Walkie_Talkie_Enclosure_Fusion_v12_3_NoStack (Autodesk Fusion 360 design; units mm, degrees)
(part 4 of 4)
sketch "Flex Rib 1.4 mm Sketch" plane through (0, 0, 0) normal (0, 0, 1) x axis (1, 0, 0)
  line L1 (16.2, 11) -> (13.8, 11)
  line L2 (17, 24.2) -> (17, 11.8)
  line L3 (13.8, 25) -> (16.2, 25)
  line L4 (13, 11.8) -> (13, 24.2)
  arc A1 centre (16.2, 11.8) radius 0.8 clockwise from (17, 11.8) to (16.2, 11)
  arc A2 centre (16.2, 24.2) radius 0.8 clockwise from (16.2, 25) to (17, 24.2)
  arc A3 centre (13.8, 24.2) radius 0.8 clockwise from (13, 24.2) to (13.8, 25)
  arc A4 centre (13.8, 11.8) radius 0.8 clockwise from (13.8, 11) to (13, 11.8)
extrude "Extrude14" add sketch "Flex Rib 1.4 mm Sketch" blind 1.4
sketch "LEFT PTT BUTTON Cap Sketch" plane through (0, 0, 0) normal (1, 0, 0) x axis (0, 0, -1)
  line L1 (-11.9, -15) -> (-12.1, -15)
  line L2 (-6, 33.1) -> (-6, -9.1)
  line L3 (-12.1, 39) -> (-11.9, 39)
  line L4 (-18, -9.1) -> (-18, 33.1)
  arc A1 centre (-11.9, -9.1) radius 5.9 clockwise from (-6, -9.1) to (-11.9, -15)
  arc A2 centre (-11.9, 33.1) radius 5.9 clockwise from (-11.9, 39) to (-6, 33.1)
  arc A3 centre (-12.1, 33.1) radius 5.9 clockwise from (-18, 33.1) to (-12.1, 39)
  arc A4 centre (-12.1, -9.1) radius 5.9 clockwise from (-12.1, -15) to (-18, -9.1)
extrude "Extrude1" new body sketch "LEFT PTT BUTTON Cap Sketch" blind -1.7 (= "-( 1.70 mm )") from offset 41
fillet "Fillet1" radius 1.2
sketch "LEFT PTT BUTTON End Guide Shoe Sketch" plane through (0, 0, 0) normal (1, 0, 0) x axis (0, 0, -1)
  line L1 (-8.2, -8.6) -> (-15.8, -8.6)
  line L2 (-7.7, -7.9) -> (-7.7, -8.1)
  line L3 (-15.8, -7.4) -> (-8.2, -7.4)
  line L4 (-16.3, -8.1) -> (-16.3, -7.9)
  arc A1 centre (-8.2, -8.1) radius 0.5 clockwise from (-7.7, -8.1) to (-8.2, -8.6)
  arc A2 centre (-8.2, -7.9) radius 0.5 clockwise from (-8.2, -7.4) to (-7.7, -7.9)
  arc A3 centre (-15.8, -7.9) radius 0.5 clockwise from (-16.3, -7.9) to (-15.8, -7.4)
  arc A4 centre (-15.8, -8.1) radius 0.5 clockwise from (-15.8, -8.6) to (-16.3, -8.1)
extrude "Extrude2" add sketch "LEFT PTT BUTTON End Guide Shoe Sketch" blind 3.75 from offset 35.75
sketch "LEFT PTT BUTTON Captive End Flange Sketch" plane through (0, 0, 0) normal (1, 0, 0) x axis (0, 0, -1)
  line L1 (-8.2, -9.2) -> (-15.8, -9.2)
  line L2 (-7.3, -7.7) -> (-7.3, -8.3)
  line L3 (-15.8, -6.8) -> (-8.2, -6.8)
  line L4 (-16.7, -8.3) -> (-16.7, -7.7)
  arc A1 centre (-8.2, -8.3) radius 0.9 clockwise from (-7.3, -8.3) to (-8.2, -9.2)
  arc A2 centre (-8.2, -7.7) radius 0.9 clockwise from (-8.2, -6.8) to (-7.3, -7.7)
  arc A3 centre (-15.8, -7.7) radius 0.9 clockwise from (-16.7, -7.7) to (-15.8, -6.8)
  arc A4 centre (-15.8, -8.3) radius 0.9 clockwise from (-15.8, -9.2) to (-16.7, -8.3)
extrude "Extrude3" add sketch "LEFT PTT BUTTON Captive End Flange Sketch" blind 1.05 from offset 34.75
sketch "LEFT PTT BUTTON End Guide Shoe Sketch (1)" plane through (0, 0, 0) normal (1, 0, 0) x axis (0, 0, -1)
  line L1 (-8.2, 31.4) -> (-15.8, 31.4)
  line L2 (-7.7, 32.1) -> (-7.7, 31.9)
  line L3 (-15.8, 32.6) -> (-8.2, 32.6)
  line L4 (-16.3, 31.9) -> (-16.3, 32.1)
  arc A1 centre (-8.2, 31.9) radius 0.5 clockwise from (-7.7, 31.9) to (-8.2, 31.4)
  arc A2 centre (-8.2, 32.1) radius 0.5 clockwise from (-8.2, 32.6) to (-7.7, 32.1)
  arc A3 centre (-15.8, 32.1) radius 0.5 clockwise from (-16.3, 32.1) to (-15.8, 32.6)
  arc A4 centre (-15.8, 31.9) radius 0.5 clockwise from (-15.8, 31.4) to (-16.3, 31.9)
extrude "Extrude4" add sketch "LEFT PTT BUTTON End Guide Shoe Sketch (1)" blind 3.75 from offset 35.75
sketch "LEFT PTT BUTTON Captive End Flange Sketch (1)" plane through (0, 0, 0) normal (1, 0, 0) x axis (0, 0, -1)
  line L1 (-8.2, 30.8) -> (-15.8, 30.8)
  line L2 (-7.3, 32.3) -> (-7.3, 31.7)
  line L3 (-15.8, 33.2) -> (-8.2, 33.2)
  line L4 (-16.7, 31.7) -> (-16.7, 32.3)
  arc A1 centre (-8.2, 31.7) radius 0.9 clockwise from (-7.3, 31.7) to (-8.2, 30.8)
  arc A2 centre (-8.2, 32.3) radius 0.9 clockwise from (-8.2, 33.2) to (-7.3, 32.3)
  arc A3 centre (-15.8, 32.3) radius 0.9 clockwise from (-16.7, 32.3) to (-15.8, 33.2)
  arc A4 centre (-15.8, 31.7) radius 0.9 clockwise from (-15.8, 30.8) to (-16.7, 31.7)
extrude "Extrude5" add sketch "LEFT PTT BUTTON Captive End Flange Sketch (1)" blind 1.05 from offset 34.75
sketch "LEFT PTT BUTTON Center Actuator Pusher Sketch" plane through (0, 0, 0) normal (1, 0, 0) x axis (0, 0, -1)
  line L1 (-14.85, 11) -> (-15.55, 11)
  line L2 (-14.2, 12.35) -> (-14.2, 11.65)
  line L3 (-15.55, 13) -> (-14.85, 13)
  line L4 (-16.2, 11.65) -> (-16.2, 12.35)
  arc A1 centre (-14.85, 11.65) radius 0.65 clockwise from (-14.2, 11.65) to (-14.85, 11)
  arc A2 centre (-14.85, 12.35) radius 0.65 clockwise from (-14.85, 13) to (-14.2, 12.35)
  arc A3 centre (-15.55, 12.35) radius 0.65 clockwise from (-16.2, 12.35) to (-15.55, 13)
  arc A4 centre (-15.55, 11.65) radius 0.65 clockwise from (-15.55, 11) to (-16.2, 11.65)
extrude "Extrude6" add sketch "LEFT PTT BUTTON Center Actuator Pusher Sketch" blind 0.8 from offset 38.65
sketch "PTT Tactile Rib 01 Sketch" plane through (0, 0, 0) normal (1, 0, 0) x axis (0, 0, -1)
  line L1 (-15.58, -11) -> (-15.62, -11)
  line L2 (-15.39, 34.81) -> (-15.39, -10.81)
  line L3 (-15.62, 35) -> (-15.58, 35)
  line L4 (-15.81, -10.81) -> (-15.81, 34.81)
  arc A1 centre (-15.58, -10.81) radius 0.19 clockwise from (-15.39, -10.81) to (-15.58, -11)
  arc A2 centre (-15.58, 34.81) radius 0.19 clockwise from (-15.58, 35) to (-15.39, 34.81)
  arc A3 centre (-15.62, 34.81) radius 0.19 clockwise from (-15.81, 34.81) to (-15.62, 35)
  arc A4 centre (-15.62, -10.81) radius 0.19 clockwise from (-15.62, -11) to (-15.81, -10.81)
extrude "Extrude7" add sketch "PTT Tactile Rib 01 Sketch" blind 0.32 from offset 40.95
sketch "PTT Tactile Rib 02 Sketch" plane through (0, 0, 0) normal (1, 0, 0) x axis (0, 0, -1)
  line L1 (-13.78, -11) -> (-13.82, -11)
  line L2 (-13.59, 34.81) -> (-13.59, -10.81)
  line L3 (-13.82, 35) -> (-13.78, 35)
  line L4 (-14.01, -10.81) -> (-14.01, 34.81)
  arc A1 centre (-13.78, -10.81) radius 0.19 clockwise from (-13.59, -10.81) to (-13.78, -11)
  arc A2 centre (-13.78, 34.81) radius 0.19 clockwise from (-13.78, 35) to (-13.59, 34.81)
  arc A3 centre (-13.82, 34.81) radius 0.19 clockwise from (-14.01, 34.81) to (-13.82, 35)
  arc A4 centre (-13.82, -10.81) radius 0.19 clockwise from (-13.82, -11) to (-14.01, -10.81)
extrude "Extrude8" add sketch "PTT Tactile Rib 02 Sketch" blind 0.32 from offset 40.95
sketch "PTT Tactile Rib 03 Sketch" plane through (0, 0, 0) normal (1, 0, 0) x axis (0, 0, -1)
  line L1 (-11.98, -11) -> (-12.02, -11)
  line L2 (-11.79, 34.81) -> (-11.79, -10.81)
  line L3 (-12.02, 35) -> (-11.98, 35)
  line L4 (-12.21, -10.81) -> (-12.21, 34.81)
  arc A1 centre (-11.98, -10.81) radius 0.19 clockwise from (-11.79, -10.81) to (-11.98, -11)
  arc A2 centre (-11.98, 34.81) radius 0.19 clockwise from (-11.98, 35) to (-11.79, 34.81)
  arc A3 centre (-12.02, 34.81) radius 0.19 clockwise from (-12.21, 34.81) to (-12.02, 35)
  arc A4 centre (-12.02, -10.81) radius 0.19 clockwise from (-12.02, -11) to (-12.21, -10.81)
extrude "Extrude9" add sketch "PTT Tactile Rib 03 Sketch" blind 0.32 from offset 40.95
sketch "PTT Tactile Rib 04 Sketch" plane through (0, 0, 0) normal (1, 0, 0) x axis (0, 0, -1)
  line L1 (-10.18, -11) -> (-10.22, -11)
  line L2 (-9.99, 34.81) -> (-9.99, -10.81)
  line L3 (-10.22, 35) -> (-10.18, 35)
  line L4 (-10.41, -10.81) -> (-10.41, 34.81)
  arc A1 centre (-10.18, -10.81) radius 0.19 clockwise from (-9.99, -10.81) to (-10.18, -11)
  arc A2 centre (-10.18, 34.81) radius 0.19 clockwise from (-10.18, 35) to (-9.99, 34.81)
  arc A3 centre (-10.22, 34.81) radius 0.19 clockwise from (-10.41, 34.81) to (-10.22, 35)
  arc A4 centre (-10.22, -10.81) radius 0.19 clockwise from (-10.22, -11) to (-10.41, -10.81)
extrude "Extrude10" add sketch "PTT Tactile Rib 04 Sketch" blind 0.32 from offset 40.95
sketch "PTT Tactile Rib 05 Sketch" plane through (0, 0, 0) normal (1, 0, 0) x axis (0, 0, -1)
  line L1 (-8.38, -11) -> (-8.42, -11)
  line L2 (-8.19, 34.81) -> (-8.19, -10.81)
  line L3 (-8.42, 35) -> (-8.38, 35)
  line L4 (-8.61, -10.81) -> (-8.61, 34.81)
  arc A1 centre (-8.38, -10.81) radius 0.19 clockwise from (-8.19, -10.81) to (-8.38, -11)
  arc A2 centre (-8.38, 34.81) radius 0.19 clockwise from (-8.38, 35) to (-8.19, 34.81)
  arc A3 centre (-8.42, 34.81) radius 0.19 clockwise from (-8.61, 34.81) to (-8.42, 35)
  arc A4 centre (-8.42, -10.81) radius 0.19 clockwise from (-8.42, -11) to (-8.61, -10.81)
extrude "Extrude11" add sketch "PTT Tactile Rib 05 Sketch" blind 0.32 from offset 40.95
sketch "VOLUME UP BUTTON Cap Sketch" plane through (0, 0, 0) normal (1, 0, 0) x axis (0, 0, -1)
  line L1 (-11.9, 13.6) -> (-12.1, 13.6)
  line L2 (-6.5, 27) -> (-6.5, 19)
  line L3 (-12.1, 32.4) -> (-11.9, 32.4)
  line L4 (-17.5, 19) -> (-17.5, 27)
  arc A1 centre (-11.9, 19) radius 5.4 clockwise from (-6.5, 19) to (-11.9, 13.6)
  arc A2 centre (-11.9, 27) radius 5.4 clockwise from (-11.9, 32.4) to (-6.5, 27)
  arc A3 centre (-12.1, 27) radius 5.4 clockwise from (-17.5, 27) to (-12.1, 32.4)
  arc A4 centre (-12.1, 19) radius 5.4 clockwise from (-12.1, 13.6) to (-17.5, 19)
extrude "Extrude1" new body sketch "VOLUME UP BUTTON Cap Sketch" blind 1.7 from offset -41
fillet "Fillet1" radius 1.2
sketch "VOLUME UP BUTTON End Guide Shoe Sketch" plane through (0, 0, 0) normal (1, 0, 0) x axis (0, 0, -1)
  line L1 (-10.5, 15.6) -> (-13.5, 15.6)
  line L2 (-10, 16.3) -> (-10, 16.1)
  line L3 (-13.5, 16.8) -> (-10.5, 16.8)
  line L4 (-14, 16.1) -> (-14, 16.3)
  arc A1 centre (-10.5, 16.1) radius 0.5 clockwise from (-10, 16.1) to (-10.5, 15.6)
  arc A2 centre (-10.5, 16.3) radius 0.5 clockwise from (-10.5, 16.8) to (-10, 16.3)
  arc A3 centre (-13.5, 16.3) radius 0.5 clockwise from (-14, 16.3) to (-13.5, 16.8)
  arc A4 centre (-13.5, 16.1) radius 0.5 clockwise from (-13.5, 15.6) to (-14, 16.1)
extrude "Extrude2" add sketch "VOLUME UP BUTTON End Guide Shoe Sketch" blind 3.75 from offset -39.5
sketch "VOLUME UP BUTTON Captive End Flange Sketch" plane through (0, 0, 0) normal (1, 0, 0) x axis (0, 0, -1)
  line L1 (-10, 15) -> (-14, 15)
  line L2 (-9.1, 16.5) -> (-9.1, 15.9)
  line L3 (-14, 17.4) -> (-10, 17.4)
  line L4 (-14.9, 15.9) -> (-14.9, 16.5)
  arc A1 centre (-10, 15.9) radius 0.9 clockwise from (-9.1, 15.9) to (-10, 15)
  arc A2 centre (-10, 16.5) radius 0.9 clockwise from (-10, 17.4) to (-9.1, 16.5)
  arc A3 centre (-14, 16.5) radius 0.9 clockwise from (-14.9, 16.5) to (-14, 17.4)
  arc A4 centre (-14, 15.9) radius 0.9 clockwise from (-14, 15) to (-14.9, 15.9)
extrude "Extrude3" add sketch "VOLUME UP BUTTON Captive End Flange Sketch" blind 1.05 from offset -35.85
sketch "VOLUME UP BUTTON End Guide Shoe Sketch (1)" plane through (0, 0, 0) normal (1, 0, 0) x axis (0, 0, -1)
  line L1 (-10.5, 29.2) -> (-13.5, 29.2)
  line L2 (-10, 29.9) -> (-10, 29.7)
  line L3 (-13.5, 30.4) -> (-10.5, 30.4)
  line L4 (-14, 29.7) -> (-14, 29.9)
  arc A1 centre (-10.5, 29.7) radius 0.5 clockwise from (-10, 29.7) to (-10.5, 29.2)
  arc A2 centre (-10.5, 29.9) radius 0.5 clockwise from (-10.5, 30.4) to (-10, 29.9)
  arc A3 centre (-13.5, 29.9) radius 0.5 clockwise from (-14, 29.9) to (-13.5, 30.4)
  arc A4 centre (-13.5, 29.7) radius 0.5 clockwise from (-13.5, 29.2) to (-14, 29.7)
extrude "Extrude4" add sketch "VOLUME UP BUTTON End Guide Shoe Sketch (1)" blind 3.75 from offset -39.5
sketch "VOLUME UP BUTTON Captive End Flange Sketch (1)" plane through (0, 0, 0) normal (1, 0, 0) x axis (0, 0, -1)
  line L1 (-10, 28.6) -> (-14, 28.6)
  line L2 (-9.1, 30.1) -> (-9.1, 29.5)
  line L3 (-14, 31) -> (-10, 31)
  line L4 (-14.9, 29.5) -> (-14.9, 30.1)
  arc A1 centre (-10, 29.5) radius 0.9 clockwise from (-9.1, 29.5) to (-10, 28.6)
  arc A2 centre (-10, 30.1) radius 0.9 clockwise from (-10, 31) to (-9.1, 30.1)
  arc A3 centre (-14, 30.1) radius 0.9 clockwise from (-14.9, 30.1) to (-14, 31)
  arc A4 centre (-14, 29.5) radius 0.9 clockwise from (-14, 28.6) to (-14.9, 29.5)
extrude "Extrude5" add sketch "VOLUME UP BUTTON Captive End Flange Sketch (1)" blind 1.05 from offset -35.85
sketch "VOLUME UP BUTTON Center Actuator Pusher Sketch" plane through (0, 0, 0) normal (1, 0, 0) x axis (0, 0, -1)
  line L1 (-14.85, 22) -> (-15.55, 22)
  line L2 (-14.2, 23.35) -> (-14.2, 22.65)
  line L3 (-15.55, 24) -> (-14.85, 24)
  line L4 (-16.2, 22.65) -> (-16.2, 23.35)
  arc A1 centre (-14.85, 22.65) radius 0.65 clockwise from (-14.2, 22.65) to (-14.85, 22)
  arc A2 centre (-14.85, 23.35) radius 0.65 clockwise from (-14.85, 24) to (-14.2, 23.35)
  arc A3 centre (-15.55, 23.35) radius 0.65 clockwise from (-16.2, 23.35) to (-15.55, 24)
  arc A4 centre (-15.55, 22.65) radius 0.65 clockwise from (-15.55, 22) to (-16.2, 22.65)
extrude "Extrude6" add sketch "VOLUME UP BUTTON Center Actuator Pusher Sketch" blind 0.8 from offset -39.45
sketch "Volume Plus Horizontal Sketch" plane through (0, 0, 0) normal (1, 0, 0) x axis (0, 0, -1)
  line L1 (-11.95, 20) -> (-12.05, 20)
  line L2 (-11.5, 25.55) -> (-11.5, 20.45)
  line L3 (-12.05, 26) -> (-11.95, 26)
  line L4 (-12.5, 20.45) -> (-12.5, 25.55)
  arc A1 centre (-11.95, 20.45) radius 0.45 clockwise from (-11.5, 20.45) to (-11.95, 20)
  arc A2 centre (-11.95, 25.55) radius 0.45 clockwise from (-11.95, 26) to (-11.5, 25.55)
  arc A3 centre (-12.05, 25.55) radius 0.45 clockwise from (-12.5, 25.55) to (-12.05, 26)
  arc A4 centre (-12.05, 20.45) radius 0.45 clockwise from (-12.05, 20) to (-12.5, 20.45)
extrude "Extrude7" add sketch "Volume Plus Horizontal Sketch" blind -0.55 (= "-( 0.55 mm )") from offset -40.9
sketch "Volume Plus Vertical Sketch" plane through (0, 0, 0) normal (1, 0, 0) x axis (0, 0, -1)
  line L1 (-9.45, 22.5) -> (-14.55, 22.5)
  line L2 (-9, 23.05) -> (-9, 22.95)
  line L3 (-14.55, 23.5) -> (-9.45, 23.5)
  line L4 (-15, 22.95) -> (-15, 23.05)
  arc A1 centre (-9.45, 22.95) radius 0.45 clockwise from (-9, 22.95) to (-9.45, 22.5)
  arc A2 centre (-9.45, 23.05) radius 0.45 clockwise from (-9.45, 23.5) to (-9, 23.05)
  arc A3 centre (-14.55, 23.05) radius 0.45 clockwise from (-15, 23.05) to (-14.55, 23.5)
  arc A4 centre (-14.55, 22.95) radius 0.45 clockwise from (-14.55, 22.5) to (-15, 22.95)
extrude "Extrude8" add sketch "Volume Plus Vertical Sketch" blind -0.55 (= "-( 0.55 mm )") from offset -40.9
sketch "VOLUME DOWN BUTTON Cap Sketch" plane through (0, 0, 0) normal (1, 0, 0) x axis (0, 0, -1)
  line L1 (-11.9, -15.4) -> (-12.1, -15.4)
  line L2 (-6.5, -2) -> (-6.5, -10)
  line L3 (-12.1, 3.4) -> (-11.9, 3.4)
  line L4 (-17.5, -10) -> (-17.5, -2)
  arc A1 centre (-11.9, -10) radius 5.4 clockwise from (-6.5, -10) to (-11.9, -15.4)
  arc A2 centre (-11.9, -2) radius 5.4 clockwise from (-11.9, 3.4) to (-6.5, -2)
  arc A3 centre (-12.1, -2) radius 5.4 clockwise from (-17.5, -2) to (-12.1, 3.4)
  arc A4 centre (-12.1, -10) radius 5.4 clockwise from (-12.1, -15.4) to (-17.5, -10)
extrude "Extrude1" new body sketch "VOLUME DOWN BUTTON Cap Sketch" blind 1.7 from offset -41
fillet "Fillet1" radius 1.2
sketch "VOLUME DOWN BUTTON End Guide Shoe Sketch" plane through (0, 0, 0) normal (1, 0, 0) x axis (0, 0, -1)
  line L1 (-10.5, -13.4) -> (-13.5, -13.4)
  line L2 (-10, -12.7) -> (-10, -12.9)
  line L3 (-13.5, -12.2) -> (-10.5, -12.2)
  line L4 (-14, -12.9) -> (-14, -12.7)
  arc A1 centre (-10.5, -12.9) radius 0.5 clockwise from (-10, -12.9) to (-10.5, -13.4)
  arc A2 centre (-10.5, -12.7) radius 0.5 clockwise from (-10.5, -12.2) to (-10, -12.7)
  arc A3 centre (-13.5, -12.7) radius 0.5 clockwise from (-14, -12.7) to (-13.5, -12.2)
  arc A4 centre (-13.5, -12.9) radius 0.5 clockwise from (-13.5, -13.4) to (-14, -12.9)
extrude "Extrude2" add sketch "VOLUME DOWN BUTTON End Guide Shoe Sketch" blind 3.75 from offset -39.5
sketch "VOLUME DOWN BUTTON Captive End Flange Sketch" plane through (0, 0, 0) normal (1, 0, 0) x axis (0, 0, -1)
  line L1 (-10, -14) -> (-14, -14)
  line L2 (-9.1, -12.5) -> (-9.1, -13.1)
  line L3 (-14, -11.6) -> (-10, -11.6)
  line L4 (-14.9, -13.1) -> (-14.9, -12.5)
  arc A1 centre (-10, -13.1) radius 0.9 clockwise from (-9.1, -13.1) to (-10, -14)
  arc A2 centre (-10, -12.5) radius 0.9 clockwise from (-10, -11.6) to (-9.1, -12.5)
  arc A3 centre (-14, -12.5) radius 0.9 clockwise from (-14.9, -12.5) to (-14, -11.6)
  arc A4 centre (-14, -13.1) radius 0.9 clockwise from (-14, -14) to (-14.9, -13.1)
extrude "Extrude3" add sketch "VOLUME DOWN BUTTON Captive End Flange Sketch" blind 1.05 from offset -35.85
sketch "VOLUME DOWN BUTTON End Guide Shoe Sketch (1)" plane through (0, 0, 0) normal (1, 0, 0) x axis (0, 0, -1)
  line L1 (-10.5, 0.2) -> (-13.5, 0.2)
  line L2 (-10, 0.9) -> (-10, 0.7)
  line L3 (-13.5, 1.4) -> (-10.5, 1.4)
  line L4 (-14, 0.7) -> (-14, 0.9)
  arc A1 centre (-10.5, 0.7) radius 0.5 clockwise from (-10, 0.7) to (-10.5, 0.2)
  arc A2 centre (-10.5, 0.9) radius 0.5 clockwise from (-10.5, 1.4) to (-10, 0.9)
  arc A3 centre (-13.5, 0.9) radius 0.5 clockwise from (-14, 0.9) to (-13.5, 1.4)
  arc A4 centre (-13.5, 0.7) radius 0.5 clockwise from (-13.5, 0.2) to (-14, 0.7)
extrude "Extrude4" add sketch "VOLUME DOWN BUTTON End Guide Shoe Sketch (1)" blind 3.75 from offset -39.5
sketch "VOLUME DOWN BUTTON Captive End Flange Sketch (1)" plane through (0, 0, 0) normal (1, 0, 0) x axis (0, 0, -1)
  line L1 (-10, -0.4) -> (-14, -0.4)
  line L2 (-9.1, 1.1) -> (-9.1, 0.5)
  line L3 (-14, 2) -> (-10, 2)
  line L4 (-14.9, 0.5) -> (-14.9, 1.1)
  arc A1 centre (-10, 0.5) radius 0.9 clockwise from (-9.1, 0.5) to (-10, -0.4)
  arc A2 centre (-10, 1.1) radius 0.9 clockwise from (-10, 2) to (-9.1, 1.1)
  arc A3 centre (-14, 1.1) radius 0.9 clockwise from (-14.9, 1.1) to (-14, 2)
  arc A4 centre (-14, 0.5) radius 0.9 clockwise from (-14, -0.4) to (-14.9, 0.5)
extrude "Extrude5" add sketch "VOLUME DOWN BUTTON Captive End Flange Sketch (1)" blind 1.05 from offset -35.85
sketch "VOLUME DOWN BUTTON Center Actuator Pusher Sketch" plane through (0, 0, 0) normal (1, 0, 0) x axis (0, 0, -1)
  line L1 (-14.85, -7) -> (-15.55, -7)
  line L2 (-14.2, -5.65) -> (-14.2, -6.35)
  line L3 (-15.55, -5) -> (-14.85, -5)
  line L4 (-16.2, -6.35) -> (-16.2, -5.65)
  arc A1 centre (-14.85, -6.35) radius 0.65 clockwise from (-14.2, -6.35) to (-14.85, -7)
  arc A2 centre (-14.85, -5.65) radius 0.65 clockwise from (-14.85, -5) to (-14.2, -5.65)
  arc A3 centre (-15.55, -5.65) radius 0.65 clockwise from (-16.2, -5.65) to (-15.55, -5)
  arc A4 centre (-15.55, -6.35) radius 0.65 clockwise from (-15.55, -7) to (-16.2, -6.35)
extrude "Extrude6" add sketch "VOLUME DOWN BUTTON Center Actuator Pusher Sketch" blind 0.8 from offset -39.45
sketch "Volume Minus Sketch" plane through (0, 0, 0) normal (1, 0, 0) x axis (0, 0, -1)
  line L1 (-11.95, -9) -> (-12.05, -9)
  line L2 (-11.5, -3.45) -> (-11.5, -8.55)
  line L3 (-12.05, -3) -> (-11.95, -3)
  line L4 (-12.5, -8.55) -> (-12.5, -3.45)
  arc A1 centre (-11.95, -8.55) radius 0.45 clockwise from (-11.5, -8.55) to (-11.95, -9)
  arc A2 centre (-11.95, -3.45) radius 0.45 clockwise from (-11.95, -3) to (-11.5, -3.45)
  arc A3 centre (-12.05, -3.45) radius 0.45 clockwise from (-12.5, -3.45) to (-12.05, -3)
  arc A4 centre (-12.05, -8.55) radius 0.45 clockwise from (-12.05, -9) to (-12.5, -8.55)
extrude "Extrude7" add sketch "Volume Minus Sketch" blind -0.55 (= "-( 0.55 mm )") from offset -40.9
base_feature "Base Feature1"
base_mesh_feature "Base Mesh Feature1"
base_feature "Base Feature1"
base_mesh_feature "Base Mesh Feature1"
base_feature "Base Feature1"
base_mesh_feature "Base Mesh Feature1"
base_feature "Base Feature1"
base_mesh_feature "Base Mesh Feature1"
base_feature "Base Feature1"
base_mesh_feature "Base Mesh Feature1"
base_feature "Base Feature1"
base_mesh_feature "Base Mesh Feature1"
base_feature "Base Feature1"
base_mesh_feature "Base Mesh Feature1"
base_feature "Base Feature1"
base_mesh_feature "Base Mesh Feature1"
base_feature "Base Feature1"
base_mesh_feature "Base Mesh Feature1"
base_feature "Base Feature1"
base_mesh_feature "Base Mesh Feature1"
base_feature "Base Feature1"
base_mesh_feature "Base Mesh Feature1"
base_feature "Base Feature1"
base_mesh_feature "Base Mesh Feature1"
base_feature "Base Feature1"
base_feature "Base Feature1"
base_feature "Base Feature1"
base_feature "Base Feature1"
base_feature "Base Feature1"
base_feature "Base Feature1"
base_feature "Base Feature1"
base_feature "Base Feature1"
base_feature "Base Feature1"
base_feature "Base Feature1"
base_feature "Base Feature1"
base_feature "Base Feature1"
base_feature "Base Feature1"
base_feature "Base Feature1"
base_feature "Base Feature1"
base_feature "Base Feature1"
base_feature "Base Feature1"
base_feature "Base Feature1"
base_feature "Base Feature1"
base_feature "Base Feature1"
base_feature "Base Feature1"
base_feature "Base Feature1"
base_feature "Base Feature1"
base_feature "Base Feature1"
base_feature "Base Feature1"
base_feature "Base Feature1"
base_feature "Base Feature1"
sketch "USB-C Plug Mating Shell Gauge Sketch" plane through (0, 0, 0) normal (1, 0, 0) x axis (0, 0, -1)
  line L1 (-15.4064, -45.2093) -> (-15.4864, -45.2093)
  line L2 (-14.2164, -38.0893) -> (-14.2164, -44.0193)
  line L3 (-15.4864, -36.8993) -> (-15.4064, -36.8993)
  line L4 (-16.6764, -44.0193) -> (-16.6764, -38.0893)
  arc A1 centre (-15.4064, -44.0193) radius 1.19 clockwise from (-14.2164, -44.0193) to (-15.4064, -45.2093)
  arc A2 centre (-15.4064, -38.0893) radius 1.19 clockwise from (-15.4064, -36.8993) to (-14.2164, -38.0893)
  arc A3 centre (-15.4864, -38.0893) radius 1.19 clockwise from (-16.6764, -38.0893) to (-15.4864, -36.8993)
  arc A4 centre (-15.4864, -44.0193) radius 1.19 clockwise from (-15.4864, -45.2093) to (-16.6764, -44.0193)
extrude "Extrude1" new body sketch "USB-C Plug Mating Shell Gauge Sketch" blind 6.65 from offset 29.8473 bodies "USB-C 6.65 mm Mating Shell"
sketch "USB-C Plug Housing Interface Gauge Sketch" plane through (0, 0, 0) normal (1, 0, 0) x axis (0, 0, -1)
  line L1 (-15.3964, -47.4793) -> (-15.4964, -47.4793)
  line L2 (-11.9464, -38.0793) -> (-11.9464, -44.0293)
  line L3 (-15.4964, -34.6293) -> (-15.3964, -34.6293)
  line L4 (-18.9464, -44.0293) -> (-18.9464, -38.0793)
  arc A1 centre (-15.3964, -44.0293) radius 3.45 clockwise from (-11.9464, -44.0293) to (-15.3964, -47.4793)
  arc A2 centre (-15.3964, -38.0793) radius 3.45 clockwise from (-15.3964, -34.6293) to (-11.9464, -38.0793)
  arc A3 centre (-15.4964, -38.0793) radius 3.45 clockwise from (-18.9464, -38.0793) to (-15.4964, -34.6293)
  arc A4 centre (-15.4964, -44.0293) radius 3.45 clockwise from (-15.4964, -47.4793) to (-18.9464, -44.0293)
extrude "Extrude2" add sketch "USB-C Plug Housing Interface Gauge Sketch" blind 5 from offset 36.2473
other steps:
create_component "CreateComponent1"
create_component "CreateComponent2"
create_component "CreateComponent3"
create_component "CreateComponent4"
create_component "CreateComponent5"
create_component "CreateComponent6"
create_component "CreateComponent7"
create_component "CreateComponent8"
create_component "CreateComponent9"
create_component "CreateComponent10"
create_component "CreateComponent11"
create_component "CreateComponent12"
create_component "CreateComponent13"
create_component "CreateComponent14"
create_component "CreateComponent15"
create_component "CreateComponent16"
create_component "CreateComponent17"
create_component "CreateComponent18"
create_component "CreateComponent19"
create_component "CreateComponent20"
create_component "CreateComponent21"
create_component "CreateComponent22"
create_component "CreateComponent1"
create_component "CreateComponent1"
create_component "CreateComponent1"
create_component "CreateComponent2"
create_component "CreateComponent1"
create_component "CreateComponent3"
create_component "CreateComponent1"
create_component "CreateComponent4"
create_component "CreateComponent1"
create_component "CreateComponent5"
create_component "CreateComponent1"
create_component "CreateComponent6"
create_component "CreateComponent1"
create_component "CreateComponent7"
create_component "CreateComponent1"
create_component "CreateComponent8"
create_component "CreateComponent1"
create_component "CreateComponent9"
create_component "CreateComponent1"
create_component "CreateComponent10"
create_component "CreateComponent1"
create_component "CreateComponent11"
create_component "CreateComponent1"
create_component "CreateComponent1"
create_component "CreateComponent2"
create_component "CreateComponent12"
create_component "CreateComponent1"
create_component "CreateComponent13"
create_component "CreateComponent1"
create_component "CreateComponent14"
create_component "CreateComponent1"
create_component "CreateComponent1"
create_component "CreateComponent2"
create_component "CreateComponent15"
create_component "CreateComponent1"
create_component "CreateComponent16"
create_component "CreateComponent1"
create_component "CreateComponent1"
create_component "CreateComponent17"
create_component "CreateComponent1"
create_component "CreateComponent18"
create_component "CreateComponent1"
create_component "CreateComponent1"
create_component "CreateComponent2"
create_component "CreateComponent3"
create_component "CreateComponent4"
create_component "CreateComponent19"
create_component "CreateComponent1"
create_component "CreateComponent20"
create_component "CreateComponent1"
create_component "CreateComponent21"
create_component "CreateComponent1"
create_component "CreateComponent22"
create_component "CreateComponent23"
named bodies: "Front Shell", "Front Cavity Tool", "Back Shell", "Back Cavity Tool", "Front Action Button", "Vertical Status Light Lens", "Prototype Tolerance Coupon", "LEFT PTT BUTTON", "VOLUME UP BUTTON", "VOLUME DOWN BUTTON", "USB-C 6.65 mm Mating Shell"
